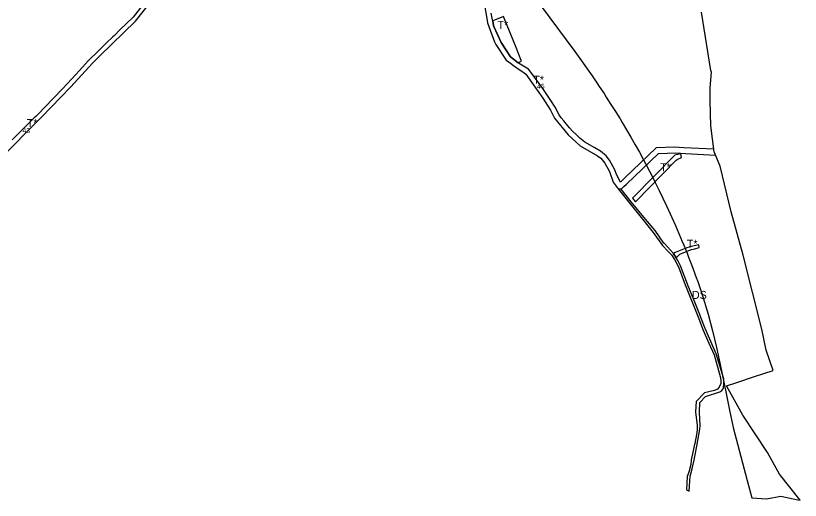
# Model space of a CAD drawing. Extents: x -535435 to -532834, y -1165802 to -1163866.
# Drawn here: x -534109 to -532834, y -1165802 to -1165015 of the extents above; entities that cross this region are included whole.
import ezdxf

# ---------------------------------------------------------------- set-up
doc = ezdxf.new("R2010")
doc.units = 0
for name, color, linetype in [('Level 15', 7, 'Continuous'), ('Level 22', 7, 'Continuous'), ('Level 23', 7, 'Continuous'), ('Level 4', 7, 'Continuous'), ('Level 61', 7, 'Continuous')]:
    doc.layers.add(name, color=color, linetype=linetype)

msp = doc.modelspace()

# ---------------------------------------------------------------- linework, layer by layer
at = {"layer": 'Level 15'}
msp.add_lwpolyline([(-533682.6, -1164422.5), (-533200.4, -1165073.2), (-533192.2, -1165084.4), (-533184.1, -1165095.7), (-533180.1, -1165101.2), (-533172.2, -1165112.6), (-533164.3, -1165124.1), (-533160.5, -1165129.8), (-533152.8, -1165141.4), (-533149.1, -1165147.1), (-533141.5, -1165158.9), (-533134.1, -1165170.6), (-533126.8, -1165182.5), (-533123.3, -1165188.4), (-533116.1, -1165200.4), (-533109.1, -1165212.4), (-533102.2, -1165224.5), (-533095.4, -1165236.7), (-533088.7, -1165249), (-533085.5, -1165255), (-533079, -1165267.4), (-533072.5, -1165279.9), (-533069.5, -1165286), (-533063.2, -1165298.6), (-533057.1, -1165311.2), (-533051.2, -1165323.8), (-533045.3, -1165336.6), (-533042.5, -1165342.8), (-533036.8, -1165355.7), (-533031.2, -1165368.5), (-533025.8, -1165381.5), (-533023.2, -1165387.8), (-533017.9, -1165400.9), (-533015.4, -1165407.3), (-533010.3, -1165420.5), (-533007.9, -1165426.9), (-533003, -1165440.1), (-533000.6, -1165446.6), (-532995.9, -1165459.8), (-532993.7, -1165466.3), (-532983.7, -1165499.8), (-532976.5, -1165526.8), (-532969.9, -1165553.8), (-532965.5, -1165574.1), (-532961.4, -1165594.5), (-532954.6, -1165628.5), (-532948.9, -1165655.5), (-532943.1, -1165683.9), (-532920.3, -1165770.2), (-532912.7, -1165798.4), (-532888.9, -1165799.8), (-532865.5, -1165795.7), (-532838, -1165801.3), (-532833.9, -1165802.2), (-532867.5, -1165759.6), (-532887.3, -1165724.4), (-532927.2, -1165664.1), (-532953.7, -1165616.3), (-532938.9, -1165611.3), (-532908.1, -1165601.1), (-532878.2, -1165591.1), (-532889.5, -1165558.1), (-532896.2, -1165523.9), (-532927, -1165404.1), (-532946, -1165333.7), (-532964.2, -1165259.5), (-532973.8, -1165236), (-532979.2, -1165193.7), (-532980.2, -1165153.1), (-532980.4, -1165132.1), (-532978.4, -1165106.4), (-532979.2, -1165103.8), (-532994.2, -1165009)], dxfattribs=at)
at = {"layer": 'Level 22'}
for points in [[(-533333.6, -1165023), (-533332.2, -1165031), (-533331.7, -1165032.2), (-533319.9, -1165058.4), (-533304.9, -1165081.8), (-533292.5, -1165091.7), (-533290.4, -1165090.6), (-533286.8, -1165088.8), (-533287.2, -1165087.6), (-533291.2, -1165077.8), (-533294.7, -1165069.3), (-533316.2, -1165016.4), (-533330.6, -1165021.9), (-533333.6, -1165023)], [(-533035.6, -1165240.9), (-533037.7, -1165241.3), (-533106.8, -1165311.4), (-533104.9, -1165313.5), (-533101.4, -1165317.3), (-533035.8, -1165249.6), (-533033.9, -1165248.6), (-533027, -1165245.2), (-533028.2, -1165239.4), (-533035.6, -1165240.9)]]:
    msp.add_lwpolyline(points, dxfattribs=at)
msp.add_lwpolyline([(-533040.1, -1165401), (-533035.6, -1165408.2), (-533029.7, -1165402.1), (-533017.8, -1165397.2), (-533017.7, -1165397.2), (-533010.6, -1165394.9), (-533005.5, -1165393.4), (-532998.2, -1165391.3), (-532999, -1165387), (-533006.3, -1165388.9), (-533010.8, -1165390), (-533018.3, -1165391.9), (-533037.4, -1165399.6)], close=True, dxfattribs=at)
at = {"layer": 'Level 23'}
for points in [[(-534136.8, -1165249.4), (-534066.7, -1165179.8), (-534019.6, -1165130.9), (-533983.5, -1165091.2), (-533971.8, -1165079.8), (-533913.8, -1165024), (-533851.8, -1164944.7)], [(-533350.7, -1164975.8), (-533343.4, -1165019.3), (-533342.2, -1165026.2), (-533337.6, -1165038.1), (-533330.5, -1165057.3), (-533328.6, -1165061.6), (-533311.9, -1165087.2), (-533304.7, -1165092.2), (-533299.9, -1165095.6), (-533290.7, -1165102), (-533282.9, -1165107), (-533280, -1165109.9), (-533252.3, -1165148.7), (-533239.7, -1165168.2), (-533233.2, -1165181.5), (-533211.2, -1165208.5), (-533191.6, -1165226.2), (-533163.2, -1165242.3), (-533157.9, -1165246.3), (-533151.3, -1165254.4), (-533143.8, -1165267.9), (-533138.1, -1165285.4), (-533129.6, -1165296), (-533125.2, -1165296.7), (-533125.2, -1165296.6), (-533120.8, -1165292.5), (-533116.4, -1165288.3), (-533064.2, -1165238.7), (-533036.3, -1165237.5), (-533020.4, -1165238.5), (-532971.5, -1165241.7), (-532973.8, -1165236), (-532974.3, -1165231.9), (-533023.4, -1165229.4), (-533038.2, -1165228.6), (-533068, -1165229.8), (-533119.1, -1165278.4), (-533126.2, -1165285.2), (-533132.6, -1165273.1), (-533135.2, -1165265.4), (-533143.8, -1165249.4), (-533149.3, -1165242.6), (-533158.3, -1165234.7), (-533167.6, -1165229.4), (-533183.9, -1165220.2), (-533192.1, -1165213.6), (-533198.2, -1165208.1), (-533203.7, -1165203.2), (-533209.1, -1165196.9), (-533213.9, -1165190.9), (-533218.3, -1165185.4), (-533222.3, -1165180.6), (-533225.9, -1165175.8), (-533232.2, -1165163.2), (-533239, -1165152.8), (-533245.6, -1165142.7), (-533252.3, -1165133.2), (-533258.3, -1165124.8), (-533264.1, -1165116.7), (-533269.9, -1165108.5), (-533275.6, -1165101.5), (-533283.8, -1165096.8), (-533291.9, -1165092.1), (-533292.5, -1165091.7), (-533304.9, -1165081.8), (-533319.9, -1165058.4), (-533331.7, -1165032.2), (-533332.2, -1165031), (-533333.6, -1165023), (-533333.9, -1165021.4), (-533336.2, -1165010.6)], [(-533902.8, -1164997.8), (-533918, -1165017.2), (-533939.3, -1165037.8), (-533948.3, -1165046.8), (-533950.9, -1165049.3), (-533961, -1165059), (-533971.3, -1165069), (-533974.8, -1165072.4), (-533990.6, -1165087.8), (-534005.5, -1165104.3), (-534010.4, -1165109.6), (-534032.6, -1165133.6), (-534061.5, -1165163.6), (-534072.1, -1165174.6), (-534075.9, -1165178.4), (-534078.6, -1165181), (-534081.2, -1165183.6), (-534101.6, -1165203.8), (-534114.2, -1165216.3)]]:
    msp.add_lwpolyline(points, dxfattribs=at)
at = {"layer": 'Level 4'}
msp.add_lwpolyline([(-533129.6, -1165296), (-533072.8, -1165367.1), (-533058, -1165388.1), (-533048.8, -1165397.7), (-533043.2, -1165403.5), (-533038.5, -1165411.1), (-533036.3, -1165414.6), (-533032, -1165423), (-533021, -1165452.3), (-533019.5, -1165456), (-533000.4, -1165503.2), (-532999.5, -1165505.5), (-532992.1, -1165524.4), (-532982.3, -1165546.9), (-532974, -1165566), (-532964.3, -1165600.9), (-532963.1, -1165607.1), (-532963.1, -1165612.6), (-532966, -1165618.2), (-532968.7, -1165621.4), (-532973.1, -1165623.6), (-532989.7, -1165627.5), (-533003.1, -1165641.4), (-533004, -1165658.5), (-533001.3, -1165680.8), (-533001.5, -1165686.5), (-533001.5, -1165687.5), (-533002.7, -1165695.5), (-533005.4, -1165709.8), (-533006.2, -1165713.6), (-533008.8, -1165726.4), (-533009.9, -1165731.5), (-533011.4, -1165736.5), (-533011.9, -1165744), (-533015, -1165756.2), (-533017.8, -1165763.5), (-533018.9, -1165785.4), (-533014.7, -1165787.2), (-533014.2, -1165779.4), (-533013.6, -1165770.3), (-533013.1, -1165762.9), (-533012, -1165759.4), (-533009.4, -1165751.2), (-533008.8, -1165748.5), (-533006.4, -1165737), (-533005, -1165730.9), (-533002.1, -1165714), (-532997.4, -1165686.8), (-532996.4, -1165681.2), (-532997.6, -1165658.9), (-532997.2, -1165643), (-532987.8, -1165633.7), (-532964.4, -1165625.7), (-532961.2, -1165623.6), (-532959.4, -1165621.2), (-532958.6, -1165620), (-532958, -1165611.3), (-532958.1, -1165604.9), (-532970.8, -1165564.4), (-532986.3, -1165528), (-532988.4, -1165523), (-532995.4, -1165505), (-532996.7, -1165501.8), (-533000.9, -1165491.3), (-533006.5, -1165477.4), (-533016.5, -1165452.8), (-533017.3, -1165450.8), (-533028.3, -1165421.3), (-533032.8, -1165412.6), (-533035.6, -1165408.2), (-533040.1, -1165401), (-533054.8, -1165385.1), (-533055.4, -1165384.2), (-533069.9, -1165364.1), (-533085.2, -1165345.4), (-533108.5, -1165317), (-533125.2, -1165296.6), (-533125.2, -1165296.7), (-533129.6, -1165296)], dxfattribs=at)

# ---------------------------------------------------------------- texts
at = {"layer": 'Level 22'}
for p in [(-533325.9, -1165036.3), (-533061.6, -1165267.6), (-533018.3, -1165391.9)]:
    msp.add_text('T*', height=13, dxfattribs=at).set_placement(p)
at = {"layer": 'Level 23'}
for p in [(-533267.7, -1165125.3), (-534090.6, -1165195.8)]:
    msp.add_text('T*', height=13, dxfattribs=at).set_placement(p)
at = {"layer": 'Level 4'}
msp.add_text('DS', height=13, dxfattribs=at).set_placement((-533010, -1165475))
at = {"layer": 'Level 61'}
for s, p in [('46', (-533261.7, -1165133.4)), ('43', (-534097.5, -1165205.6))]:
    msp.add_text(s, height=8, dxfattribs=at).set_placement(p)

doc.saveas('drawing.dxf')
